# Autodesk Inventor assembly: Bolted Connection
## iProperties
Created: 2011-05
Part Number: Bolted Connection
Document SubType Name: Assembly
Designer: 904Chiaki
ClientObjectVersion: 1
Author: 904Chiaki
